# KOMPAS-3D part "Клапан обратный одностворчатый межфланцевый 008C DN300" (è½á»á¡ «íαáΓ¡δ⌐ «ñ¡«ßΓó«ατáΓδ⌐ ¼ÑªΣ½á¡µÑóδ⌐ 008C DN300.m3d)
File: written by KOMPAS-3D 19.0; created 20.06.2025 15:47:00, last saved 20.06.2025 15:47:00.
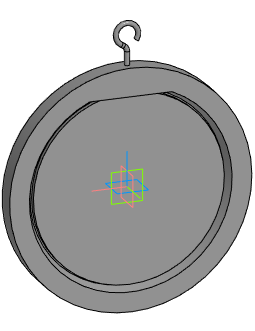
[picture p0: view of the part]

Document properties: Полное имя файла: E:\Dendor Работа Сачек\3D для проектировщиков\5.1 Тип 008C. Клапан обратный одностворчатый межфланцевый\stp_Клапан обратный одностворчатый межфланцевый 008C\Клапан обратный одностворчатый межфланцевый 008C DN300.m3d

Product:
- Part/product: Клапан обратный одностворчатый межфланцевый 008C DN300

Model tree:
1. Операция без истории:1  (labels: Клапан обратный одностворчатый межфланцевый 008C DN300)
